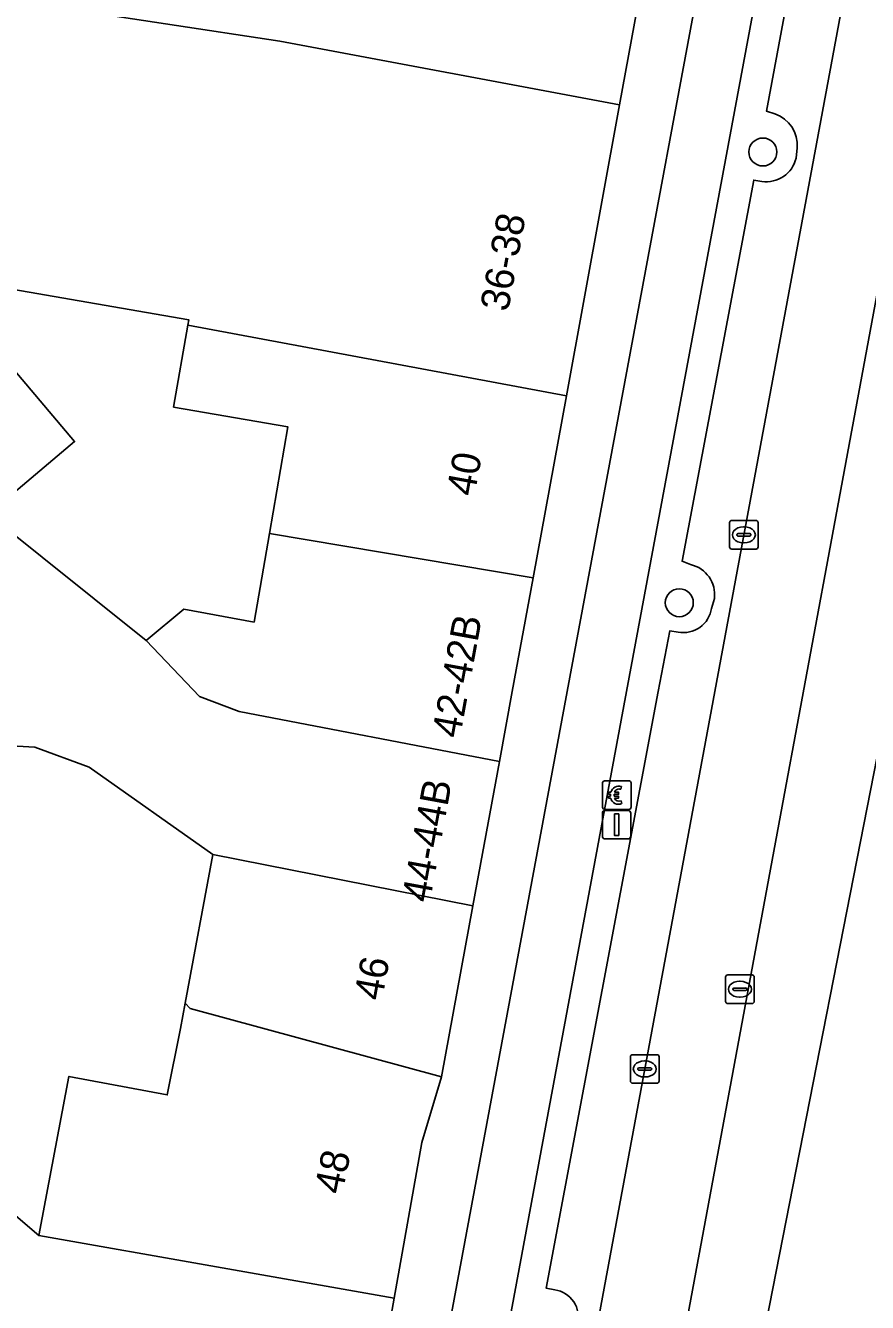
# Model space of a CAD drawing. Extents: x 161402 to 161933, y 381647 to 382315.
# Drawn here: x 161879.81 to 161909.25, y 381978.64 to 382023.29 of the extents above; entities that cross this region are included whole.
import ezdxf

# ---------------------------------------------------------------- set-up
doc = ezdxf.new("R2010")
doc.units = 0
for name, color, linetype in [('IMGEO_Betaalautomaat', 7, 'Continuous'), ('IMGEO_Boom', 7, 'Continuous'), ('IMGEO_Erf', 7, 'Continuous'), ('IMGEO_Fietspad_gesloten', 7, 'Continuous'), ('IMGEO_Kolk', 7, 'Continuous'), ('IMGEO_Lichtmast', 7, 'Continuous'), ('IMGEO_OVBaan_gesloten', 7, 'Continuous'), ('IMGEO_Pand', 7, 'Continuous'), ('IMGEO_Pand_nummerreeks', 7, 'Continuous'), ('IMGEO_Parkeervlak_open', 7, 'Continuous'), ('IMGEO_Rijbaan_lokaal_gesloten', 7, 'Continuous'), ('IMGEO_Rioolput', 7, 'Continuous'), ('IMGEO_Verkeerseiland_open', 7, 'Continuous'), ('IMGEO_Voetpad_open', 7, 'Continuous')]:
    doc.layers.add(name, color=color, linetype=linetype)

msp = doc.modelspace()

# ---------------------------------------------------------------- linework, layer by layer
at = {"layer": 'IMGEO_Betaalautomaat'}
for p, q in [((161899.985, 381995.955), (161899.985, 381996.796)), ((161899.985, 381996.796), (161899.985, 381995.955)), ((161900.06, 381996.879), (161900.901, 381996.879)), ((161900.901, 381996.879), (161900.06, 381996.879)), ((161900.984, 381996.805), (161900.984, 381995.964)), ((161900.984, 381995.964), (161900.984, 381996.805)), ((161900.268, 381996.343), (161900.268, 381996.411)), ((161900.389, 381996.411), (161900.389, 381996.343)), ((161900.647, 381996.684), (161900.63, 381996.584)), ((161900.634, 381996.178), (161900.656, 381996.091)), ((161900.91, 381995.88), (161900.069, 381995.88)), ((161900.069, 381995.88), (161900.91, 381995.88))]:
    msp.add_line(p, q, dxfattribs=at)
for points in [[(161900.268, 381996.411), (161900.199, 381996.411), (161900.199, 381996.48), (161900.278, 381996.48)], [(161900.273, 381996.274), (161900.199, 381996.274), (161900.199, 381996.343), (161900.268, 381996.343)], [(161900.4, 381996.48), (161900.547, 381996.48), (161900.547, 381996.411), (161900.389, 381996.411)], [(161900.389, 381996.343), (161900.547, 381996.343), (161900.547, 381996.274), (161900.403, 381996.274)]]:
    msp.add_lwpolyline(points, dxfattribs=at)
for centre, radius, start, end in [((161900.063, 381996.802), 0.0779, 92.4484, 184.2845), ((161900.063, 381996.802), 0.0779, 92.4484, 184.2845), ((161900.907, 381996.802), 0.0779, 2.4484, 94.2845), ((161900.907, 381996.802), 0.0779, 2.4484, 94.2845), ((161900.561, 381996.404), 0.293, 73.014, 165.0139), ((161900.567, 381996.417), 0.179, 69.3236, 159.5683), ((161900.063, 381995.958), 0.0779, 182.4484, 274.2845), ((161900.063, 381995.958), 0.0779, 182.4484, 274.2845), ((161900.534, 381996.329), 0.267, 191.8096, 297.0389), ((161900.567, 381996.344), 0.179, 202.7625, 291.8693), ((161900.907, 381995.958), 0.0779, 272.4484, 4.2845), ((161900.907, 381995.958), 0.0779, 272.4484, 4.2845)]:
    msp.add_arc(centre, radius, start, end, dxfattribs=at)
at = {"layer": 'IMGEO_Boom'}
for centre in [(161905.593, 382018.864), (161902.671, 382003.107)]:
    msp.add_circle(centre, 0.489, dxfattribs=at)
at = {"layer": 'IMGEO_Erf'}
for points in [[(161884.99, 382009.944), (161885.484, 382012.805), (161885.518, 382013.001), (161876.089, 382014.631), (161875.942, 382013.78), (161879.179, 382013.22), (161878.935, 382011.811), (161881.528, 382008.741), (161879.399, 382006.944), (161879.107, 382007.258), (161873.713, 382013.349), (161873.17, 382010.475), (161884.026, 382001.783), (161885.351, 382002.88), (161887.804, 382002.429), (161888.339, 382005.521), (161888.984, 382009.253)], [(161882.034, 381997.356), (161880.142, 381998.056), (161879.115, 381998.117), (161877.576, 382000), (161874.692, 382003.53), (161872.441, 382006.571), (161871.243, 382000), (161871.144, 381999.457), (161875.859, 381994.892), (161875.679, 381993.882), (161874.432, 381986.902), (161874.288, 381986.095), (161880.283, 381980.984), (161881.327, 381986.546), (161884.769, 381985.9), (161885.227, 381988.221), (161885.393, 381989.112), (161886.356, 381994.299)]]:
    msp.add_lwpolyline(points, close=True, dxfattribs=at)
at = {"layer": 'IMGEO_Fietspad_gesloten'}
for points in [[(161910.061, 382061.001), (161905.702, 382037.375), (161898.752, 382000), (161887.89, 381941.593), (161886.669, 381935.154), (161880.56, 381902.497), (161879.486, 381896.758), (161857.65, 381780.798), (161851.928, 381750), (161842.232, 381697.819)], [(161881.54, 381896.271), (161882.623, 381902.093), (161888.398, 381933.147), (161890.059, 381942.083), (161900.83, 382000), (161908.061, 382038.88), (161912.039, 382060.567)]]:
    msp.add_lwpolyline(points, dxfattribs=at)
at = {"layer": 'IMGEO_Kolk'}
for p, q in [((161904.427, 382005.056), (161904.427, 382005.908)), ((161904.502, 382005.982), (161905.354, 382005.982)), ((161904.915, 382005.762), (161904.94, 382005.762)), ((161905.428, 382005.908), (161905.428, 382005.056)), ((161904.686, 382005.476), (161904.686, 382005.488)), ((161905.124, 382005.439), (161904.726, 382005.439)), ((161904.729, 382005.525), (161905.127, 382005.525)), ((161905.17, 382005.488), (161905.17, 382005.476)), ((161905.354, 382004.982), (161904.502, 382004.982)), ((161904.938, 382005.202), (161904.913, 382005.202)), ((161900.963, 381986.38), (161900.963, 381987.232)), ((161901.038, 381987.306), (161901.89, 381987.306)), ((161901.451, 381987.086), (161901.476, 381987.086)), ((161901.964, 381987.232), (161901.964, 381986.38)), ((161901.222, 381986.8), (161901.222, 381986.812)), ((161901.66, 381986.763), (161901.262, 381986.763)), ((161901.265, 381986.849), (161901.663, 381986.849)), ((161901.474, 381986.526), (161901.449, 381986.526)), ((161901.706, 381986.812), (161901.706, 381986.8)), ((161901.89, 381986.306), (161901.038, 381986.306))]:
    msp.add_line(p, q, dxfattribs=at)
for points in [[(161904.427, 382005.056), (161904.427, 382005.908)], [(161904.502, 382005.982), (161905.354, 382005.982)], [(161905.428, 382005.908), (161905.428, 382005.056)], [(161905.354, 382004.982), (161904.502, 382004.982)], [(161900.963, 381986.38), (161900.963, 381987.232)], [(161901.038, 381987.306), (161901.89, 381987.306)], [(161901.964, 381987.232), (161901.964, 381986.38)], [(161901.89, 381986.306), (161901.038, 381986.306)]]:
    msp.add_lwpolyline(points, dxfattribs=at)
for centre, radius, start, end in [((161904.504, 382005.906), 0.0765, 91.552, 178.448), ((161904.504, 382005.906), 0.0765, 91.552, 178.448), ((161905.352, 382005.906), 0.0765, 1.552, 88.448), ((161905.352, 382005.906), 0.0765, 1.552, 88.448), ((161904.726, 382005.485), 0.0403, 85.8775, 175.7526), ((161904.723, 382005.475), 0.0366, 178.938, 274.7102), ((161905.127, 382005.482), 0.043, 264.8664, 352.4533), ((161905.131, 382005.487), 0.0386, 1.7309, 96.639), ((161904.504, 382005.058), 0.0765, 181.552, 268.448), ((161904.504, 382005.058), 0.0765, 181.552, 268.448), ((161905.352, 382005.058), 0.0765, 271.552, 358.448), ((161905.352, 382005.058), 0.0765, 271.552, 358.448), ((161901.04, 381987.23), 0.0765, 91.552, 178.448), ((161901.04, 381987.23), 0.0765, 91.552, 178.448), ((161901.888, 381987.23), 0.0765, 1.552, 88.448), ((161901.888, 381987.23), 0.0765, 1.552, 88.448), ((161901.262, 381986.809), 0.0403, 85.8775, 175.7526), ((161901.259, 381986.799), 0.0366, 178.938, 274.7102), ((161901.663, 381986.806), 0.043, 264.8664, 352.4533), ((161901.667, 381986.811), 0.0386, 1.7309, 96.639), ((161901.04, 381986.382), 0.0765, 181.552, 268.448), ((161901.04, 381986.382), 0.0765, 181.552, 268.448), ((161901.888, 381986.382), 0.0765, 271.552, 358.448), ((161901.888, 381986.382), 0.0765, 271.552, 358.448)]:
    msp.add_arc(centre, radius, start, end, dxfattribs=at)
for centre, major_axis, ratio, start_param, end_param in [((161904.914, 382005.482), (-0.387, 0.002), 0.722429, 4.712389, 7.853982), ((161904.939, 382005.482), (-0.39, 0.002), 0.717154, 1.570796, 4.712389), ((161901.45, 381986.806), (-0.387, 0.002), 0.722429, 4.712389, 7.853982), ((161901.475, 381986.806), (-0.39, 0.002), 0.717154, 1.570796, 4.712389)]:
    msp.add_ellipse(centre, major_axis=major_axis, ratio=ratio, start_param=start_param, end_param=end_param, dxfattribs=at)
at = {"layer": 'IMGEO_Lichtmast'}
for p, q in [((161899.982, 381994.947), (161899.982, 381995.747)), ((161899.982, 381995.747), (161899.982, 381994.947)), ((161900.082, 381995.847), (161900.872, 381995.847)), ((161900.872, 381995.847), (161900.082, 381995.847)), ((161900.972, 381995.747), (161900.972, 381994.947)), ((161900.972, 381994.947), (161900.972, 381995.747)), ((161900.872, 381994.847), (161900.082, 381994.847)), ((161900.082, 381994.847), (161900.872, 381994.847))]:
    msp.add_line(p, q, dxfattribs=at)
msp.add_lwpolyline([(161900.402, 381995.722), (161900.552, 381995.722), (161900.552, 381994.972), (161900.402, 381994.972), (161900.402, 381995.722)], dxfattribs=at)
for centre, start, end in [((161900.082, 381995.747), 90, 180), ((161900.082, 381995.747), 90, 180), ((161900.872, 381995.747), 0, 90), ((161900.872, 381995.747), 360, 90), ((161900.082, 381994.947), 180, 270), ((161900.082, 381994.947), 180, 270), ((161900.872, 381994.947), 270, 0), ((161900.872, 381994.947), 270, 0)]:
    msp.add_arc(centre, 0.1, start, end, dxfattribs=at)
at = {"layer": 'IMGEO_OVBaan_gesloten'}
for points in [[(161847.327, 381677.629), (161847.814, 381679.325), (161869.795, 381786.79), (161883.773, 381866.122), (161911.481, 382007.357), (161916.93, 382035.129), (161933.101, 382124.399), (161931.462, 382125.963), (161930.949, 382121.39)], [(161929.574, 382113.249), (161927.659, 382104.365), (161926.989, 382101.276), (161926.695, 382099.95), (161920.797, 382074.121), (161920.568, 382072.989), (161920.066, 382070.485), (161894.174, 381930.698), (161894.155, 381930.593), (161893.956, 381929.536), (161893.492, 381927.072), (161889.963, 381908.334), (161866.208, 381782.197), (161866.199, 381782.149), (161865.069, 381776.053), (161864.537, 381773.18), (161864.311, 381771.961), (161856.328, 381728.885)]]:
    msp.add_lwpolyline(points, dxfattribs=at)
at = {"layer": 'IMGEO_Pand'}
for points in [[(161902.704, 382032.073), (161895.4, 382033.445), (161895.112, 382031.912), (161889.378, 382032.986), (161878.84, 382034.96), (161874.211, 382035.706), (161874.485, 382031.994), (161874.247, 382030.726), (161879.703, 382024.079), (161880.709, 382023.945), (161888.702, 382022.741), (161900.585, 382020.509)], [(161898.721, 382010.338), (161885.484, 382012.805), (161884.99, 382009.944), (161888.984, 382009.253), (161888.339, 382005.521), (161897.556, 382003.977)], [(161885.901, 381999.826), (161884.026, 382001.783), (161873.17, 382010.475), (161872.441, 382006.571), (161874.692, 382003.53), (161877.576, 382000), (161879.115, 381998.117), (161880.142, 381998.056), (161882.034, 381997.356), (161886.356, 381994.299), (161895.455, 381992.511), (161896.379, 381997.555), (161887.286, 381999.308)], [(161897.556, 382003.977), (161888.339, 382005.521), (161887.804, 382002.429), (161885.351, 382002.88), (161884.026, 382001.783), (161885.901, 381999.826), (161887.286, 381999.308), (161896.379, 381997.555), (161896.827, 382000)], [(161885.393, 381989.112), (161885.565, 381988.922), (161894.351, 381986.526), (161895.455, 381992.511), (161886.356, 381994.299)], [(161880.283, 381980.984), (161874.288, 381986.095), (161874.432, 381986.902), (161869.626, 381991.167), (161866.912, 381976.352), (161867.399, 381976.257), (161868.882, 381977.766), (161869.113, 381978.001), (161869.163, 381978.052), (161879.974, 381976.006), (161891.821, 381973.764), (161892.707, 381978.796)], [(161885.393, 381989.112), (161885.227, 381988.221), (161884.769, 381985.9), (161881.327, 381986.546), (161880.283, 381980.984), (161892.707, 381978.796), (161893.665, 381984.233), (161894.351, 381986.526), (161885.565, 381988.922)]]:
    msp.add_lwpolyline(points, close=True, dxfattribs=at)
msp.add_lwpolyline([(161863.131, 382023.567), (161869.815, 382022.328), (161867.411, 382008.805), (161867.662, 382008.757), (161868.345, 382012.335), (161869.732, 382012.161), (161873.713, 382013.349), (161879.107, 382007.258), (161879.399, 382006.944), (161881.528, 382008.741), (161878.935, 382011.811), (161879.179, 382013.22), (161875.942, 382013.78), (161876.089, 382014.631), (161885.518, 382013.001), (161885.484, 382012.805), (161898.721, 382010.338), (161900.585, 382020.509), (161888.702, 382022.741), (161880.709, 382023.945)], dxfattribs=at)
at = {"layer": 'IMGEO_Parkeervlak_open'}
for points in [[(161894.985, 381951.871), (161903.912, 382000), (161910.924, 382037.806), (161917.217, 382071.563)], [(161909.017, 382036.526), (161908.748, 382036.59), (161905.714, 382020.292), (161906.013, 382020.197)], [(161906.794, 382019.011), (161906.752, 382018.65)], [(161905.552, 382017.835), (161905.275, 382017.882), (161902.77, 382004.559), (161903.065, 382004.44)], [(161903.898, 382003.256), (161903.796, 382002.91)], [(161902.629, 382002.08), (161902.336, 382002.121), (161901.937, 382000), (161898.016, 381979.138), (161898.32, 381979.083)]]:
    msp.add_lwpolyline(points, dxfattribs=at)
for centre, radius, start, end in [((161905.641, 382019.102), 1.157, 355.5035, 71.2275), ((161905.716, 382018.885), 1.062, 261.1287, 347.2374), ((161902.829, 382003.389), 1.077, 352.8981, 77.3583), ((161902.817, 382003.051), 0.989, 259.0601, 351.7827), ((161898.185, 381978.134), 0.958, 346.3441, 81.887)]:
    msp.add_arc(centre, radius, start, end, dxfattribs=at)
at = {"layer": 'IMGEO_Rijbaan_lokaal_gesloten'}
for points in [[(161894.174, 381930.698), (161920.066, 382070.485), (161920.568, 382072.989), (161920.797, 382074.121), (161926.695, 382099.95)], [(161917.217, 382071.563), (161910.924, 382037.806), (161903.912, 382000), (161894.985, 381951.871), (161894.088, 381946.96), (161893.853, 381945.73)]]:
    msp.add_lwpolyline(points, dxfattribs=at)
at = {"layer": 'IMGEO_Rioolput'}
for p, q in [((161904.364, 381990.094), (161905.216, 381990.094)), ((161904.289, 381989.168), (161904.289, 381990.02)), ((161904.591, 381989.637), (161904.989, 381989.637)), ((161904.777, 381989.874), (161904.802, 381989.874)), ((161905.29, 381990.02), (161905.29, 381989.168)), ((161904.548, 381989.588), (161904.548, 381989.6)), ((161904.986, 381989.551), (161904.588, 381989.551)), ((161904.8, 381989.314), (161904.775, 381989.314)), ((161905.032, 381989.6), (161905.032, 381989.588)), ((161905.216, 381989.094), (161904.364, 381989.094))]:
    msp.add_line(p, q, dxfattribs=at)
for points in [[(161904.364, 381990.094), (161905.216, 381990.094)], [(161904.289, 381989.168), (161904.289, 381990.02)], [(161905.29, 381990.02), (161905.29, 381989.168)], [(161905.216, 381989.094), (161904.364, 381989.094)]]:
    msp.add_lwpolyline(points, dxfattribs=at)
for centre, radius, start, end in [((161904.366, 381990.018), 0.0765, 91.552, 178.448), ((161904.366, 381990.018), 0.0765, 91.552, 178.448), ((161905.214, 381990.018), 0.0765, 1.552, 88.448), ((161905.214, 381990.018), 0.0765, 1.552, 88.448), ((161904.588, 381989.597), 0.0403, 85.8775, 175.7526), ((161904.993, 381989.599), 0.0386, 1.7309, 96.639), ((161904.585, 381989.587), 0.0366, 178.938, 274.7102), ((161904.989, 381989.594), 0.043, 264.8664, 352.4533), ((161904.366, 381989.17), 0.0765, 181.552, 268.448), ((161904.366, 381989.17), 0.0765, 181.552, 268.448), ((161905.214, 381989.17), 0.0765, 271.552, 358.448), ((161905.214, 381989.17), 0.0765, 271.552, 358.448)]:
    msp.add_arc(centre, radius, start, end, dxfattribs=at)
for centre, major_axis, ratio, start_param, end_param in [((161904.776, 381989.594), (-0.387, 0.002), 0.722429, 4.712389, 7.853982), ((161904.801, 381989.594), (-0.39, 0.002), 0.717154, 1.570796, 4.712389)]:
    msp.add_ellipse(centre, major_axis=major_axis, ratio=ratio, start_param=start_param, end_param=end_param, dxfattribs=at)
at = {"layer": 'IMGEO_Verkeerseiland_open'}
for points in [[(161912.039, 382060.567), (161908.061, 382038.88), (161900.83, 382000), (161890.059, 381942.083), (161888.398, 381933.147), (161882.623, 381902.093), (161881.54, 381896.271), (161869.899, 381834.602), (161872.587, 381834.08), (161872.769, 381835.211)], [(161906.013, 382020.197), (161905.714, 382020.292), (161908.748, 382036.59), (161909.017, 382036.526)], [(161906.752, 382018.65), (161906.794, 382019.011)], [(161903.065, 382004.44), (161902.77, 382004.559), (161905.275, 382017.882), (161905.552, 382017.835)], [(161903.796, 382002.91), (161903.898, 382003.256)], [(161898.32, 381979.083), (161898.016, 381979.138), (161901.937, 382000), (161902.336, 382002.121), (161902.629, 382002.08)]]:
    msp.add_lwpolyline(points, dxfattribs=at)
for centre, radius, start, end in [((161905.641, 382019.102), 1.157, 355.5035, 71.2275), ((161905.716, 382018.885), 1.062, 261.1287, 347.2374), ((161902.829, 382003.389), 1.077, 352.8981, 77.3583), ((161902.817, 382003.051), 0.989, 259.0601, 351.7827), ((161898.185, 381978.134), 0.958, 346.3441, 81.887)]:
    msp.add_arc(centre, radius, start, end, dxfattribs=at)
at = {"layer": 'IMGEO_Voetpad_open'}
for points in [[(161907.56, 382076.762), (161907.356, 382074.185), (161905.504, 382047.572), (161905.48, 382047.22), (161903.899, 382038.59), (161902.704, 382032.073), (161900.585, 382020.509), (161898.721, 382010.338), (161897.556, 382003.977), (161896.827, 382000), (161896.379, 381997.555), (161895.455, 381992.511), (161894.351, 381986.526), (161893.665, 381984.233), (161892.707, 381978.796), (161891.821, 381973.764), (161889.826, 381962.441), (161889.787, 381962.219), (161888.825, 381956.914), (161887.991, 381952.322), (161887.211, 381948.02), (161886.859, 381948.049)], [(161887.89, 381941.593), (161898.752, 382000), (161905.702, 382037.375), (161910.061, 382061.001)]]:
    msp.add_lwpolyline(points, dxfattribs=at)

# ---------------------------------------------------------------- texts
at = {"layer": 'IMGEO_Pand_nummerreeks'}
for s, rotation, p in [('36-38', 79.5448, (161896.684, 382013.253)), ('40', 79.7328, (161895.506, 382006.798)), ('42-42B', 79.6125, (161894.998, 381998.34)), ('44-44B', 79.6182, (161893.945, 381992.593)), ('46', 79.5486, (161892.274, 381989.163)), ('48', 78.3554, (161890.882, 381982.391))]:
    msp.add_text(s, height=1, rotation=rotation, dxfattribs=at).set_placement(p)

doc.saveas('drawing.dxf')
